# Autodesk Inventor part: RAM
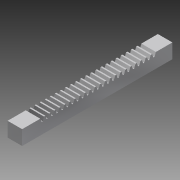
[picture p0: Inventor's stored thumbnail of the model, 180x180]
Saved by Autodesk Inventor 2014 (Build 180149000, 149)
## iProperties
Shininess: 64.0
Length Units: 11272
Angle Units: 11279
Time Units: 11290
Mass Units: 11286
Length Display Precision: 3
Angle Display Precision: 2
Compacted: True
Part Number: RAM
Document SubType Name: Modeling
Created: 2003-11
Designer: Autodesk, Inc.
Manufacturer: Standard
Standards Organization: Custom
Mass: 509.763 g
Surface Area: 178.528 cm^2
Volume: 65.0208 cm^3
Density: 7.84 g/cm^3
Material: Steel, High Strength Low Alloy
Appearance: Chrome
Density: 0.0
Volumn: 0.0
Area: 0.0
PropertySet Name: Model Information
Control State: 0
Master: False
Checked Out: False
Author: Autodesk, Inc.
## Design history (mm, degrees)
sketch "Sketch1"
  geometry: L1 (0, 0)-(19.05, 0); L2 (19.05, 0)-(19.05, 19.05); L3 (19.05, 19.05)-(0, 19.05); L4 (0, 19.05)-(0, 0)
  constraints: 8 end point, 2 parallel, 1 horizontal, 1 perpendicular
  dimensions: "d0" = 19.05 distance of L1.start L1.end; "d1" = 19.05 distance of L1.end L2.end
extrude "Extrusion1" new body sketch "Sketch1" distance "d2" = 196.85; taper "d3" = 0 deg
sketch "Sketch2"
  geometry: L1 (0, 0)-(0, 19.05) reference; L2 (0, 19.05)-(-196.85, 19.05) reference; L3 (-196.85, 19.05)-(-196.85, 0) reference; L4 (0, 0)-(-196.85, 0) reference; L5 (-168.185, 19.05)-(-166.4, 19.05); L6 (-166.4, 19.05)-(-164.739, 14.486); L7 (-168.185, 19.05)-(-169.846, 14.486); L8 (-167.293, 19.05)-(-167.293, 27.541); L9 (-130.145, 19.823)-(-130.145, 4.561); L10 (-173.431, 16.934)-(-94.815, 16.934); L11 (-163.197, 14.486)-(-161.535, 19.05); L12 (-161.535, 19.05)-(-159.751, 19.05); L13 (-159.751, 19.05)-(-158.089, 14.486); L14 (-164.739, 14.486)-(-163.197, 14.486); L15 (-158.089, 14.486)-(-24.993, 14.486); L16 (-160.643, 19.05)-(-160.643, 25.268); L17 (-169.846, 14.486)-(-171.389, 14.486); L18 (-171.389, 14.486)-(-173.05, 19.05); L19 (-156.542, 14.486)-(-154.881, 19.05); L20 (-154.881, 19.05)-(-153.096, 19.05); L21 (-153.096, 19.05)-(-151.435, 14.486); L22 (-149.887, 14.486)-(-148.226, 19.05); L23 (-148.226, 19.05)-(-146.441, 19.05); L24 (-146.441, 19.05)-(-144.78, 14.486); L25 (-143.232, 14.486)-(-141.571, 19.05); L26 (-141.571, 19.05)-(-139.786, 19.05); L27 (-139.786, 19.05)-(-138.125, 14.486); L28 (-136.578, 14.486)-(-134.916, 19.05); L29 (-134.916, 19.05)-(-133.132, 19.05); L30 (-133.132, 19.05)-(-131.47, 14.486); L31 (-129.923, 14.486)-(-128.261, 19.05); L32 (-128.261, 19.05)-(-126.477, 19.05); L33 (-126.477, 19.05)-(-124.815, 14.486); L34 (-123.268, 14.486)-(-121.607, 19.05); L35 (-121.607, 19.05)-(-119.822, 19.05); L36 (-119.822, 19.05)-(-118.161, 14.486); L37 (-116.613, 14.486)-(-114.952, 19.05); L38 (-114.952, 19.05)-(-113.167, 19.05); L39 (-113.167, 19.05)-(-111.506, 14.486); L40 (-109.958, 14.486)-(-108.297, 19.05); L41 (-108.297, 19.05)-(-106.512, 19.05); L42 (-106.512, 19.05)-(-104.851, 14.486); L43 (-103.304, 14.486)-(-101.642, 19.05); L44 (-101.642, 19.05)-(-99.858, 19.05); L45 (-99.858, 19.05)-(-98.196, 14.486); L46 (-96.649, 14.486)-(-94.987, 19.05); L47 (-94.987, 19.05)-(-93.203, 19.05); L48 (-93.203, 19.05)-(-91.541, 14.486); L49 (-89.994, 14.486)-(-88.333, 19.05); L50 (-88.333, 19.05)-(-86.548, 19.05); L51 (-86.548, 19.05)-(-84.887, 14.486); L52 (-83.339, 14.486)-(-81.678, 19.05); L53 (-81.678, 19.05)-(-79.893, 19.05); L54 (-79.893, 19.05)-(-78.232, 14.486); L55 (-76.684, 14.486)-(-75.023, 19.05); L56 (-75.023, 19.05)-(-73.238, 19.05); L57 (-73.238, 19.05)-(-71.577, 14.486); L58 (-70.03, 14.486)-(-68.368, 19.05); L59 (-68.368, 19.05)-(-66.584, 19.05); L60 (-66.584, 19.05)-(-64.922, 14.486); L61 (-63.375, 14.486)-(-61.713, 19.05); L62 (-61.713, 19.05)-(-59.929, 19.05); L63 (-59.929, 19.05)-(-58.267, 14.486); L64 (-56.72, 14.486)-(-55.059, 19.05)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; 65 further points
  constraints: 201 end point, 53 point on line, 27 collinear, 10 parallel, 3 perpendicular, 2 midpoint, 1 coincident, 1 horizontal, 200 other
  dimensions: "d5" = 2.11582 distance between parallel lines of L10 L5; "d6" = 20 deg angle of L8 L7; "d7" = 20 deg angle of L6 L8; "d11" = 6.64972 distance between parallel lines of L16 L8; "d12" = 3.32486 distance of point (-165.63, 16.934) point (-168.955, 16.934); "d13" = 3.32486 distance of point (-158.981, 16.934) point (-162.306, 16.934) (= d12); "d14" = 3.32486 distance of point (-168.955, 16.934) point (-172.28, 16.934) (= d12); "d15" = 23.7998 distance from line of L3 L18.end; "d16" = 2.44856 distance between parallel lines of L17 L10; "d19" = 6.6548 distance of L11.start L19.start
extrude "Extrusion2" sketch "Sketch2" stored distance "d24" = 25.4; taper "d25" = 0 deg
sketch "Sketch5"
  geometry: L1 (126.82, 14.486)-(128.482, 19.05) reference; L2 (125.273, 14.486)-(126.82, 14.486) reference; L3 (123.612, 19.05)-(125.273, 14.486) reference; L4 (123.612, 19.05)-(121.827, 19.05) reference; L5 (120.166, 14.486)-(121.827, 19.05) reference; L6 (118.618, 14.486)-(120.166, 14.486) reference; L7 (116.957, 19.05)-(118.618, 14.486) reference; L8 (116.957, 19.05)-(115.172, 19.05) reference; L9 (113.511, 14.486)-(115.172, 19.05) reference; L10 (111.963, 14.486)-(113.511, 14.486) reference; L11 (110.302, 19.05)-(111.963, 14.486) reference; L12 (110.302, 19.05)-(108.517, 19.05) reference; L13 (106.856, 14.486)-(108.517, 19.05) reference; L14 (105.309, 14.486)-(106.856, 14.486) reference; L15 (103.647, 19.05)-(105.309, 14.486) reference; L16 (103.647, 19.05)-(101.863, 19.05) reference; L17 (100.201, 14.486)-(101.863, 19.05) reference; L18 (98.654, 14.486)-(100.201, 14.486) reference; L19 (96.992, 19.05)-(98.654, 14.486) reference; L20 (96.992, 19.05)-(95.208, 19.05) reference; L21 (93.546, 14.486)-(95.208, 19.05) reference; L22 (91.999, 14.486)-(93.546, 14.486) reference; L23 (90.338, 19.05)-(91.999, 14.486) reference; L24 (90.338, 19.05)-(88.553, 19.05) reference; L25 (86.892, 14.486)-(88.553, 19.05) reference; L26 (85.344, 14.486)-(86.892, 14.486) reference; L27 (83.683, 19.05)-(85.344, 14.486) reference; L28 (83.683, 19.05)-(81.898, 19.05) reference; L29 (80.237, 14.486)-(81.898, 19.05) reference; L30 (78.689, 14.486)-(80.237, 14.486) reference; L31 (77.028, 19.05)-(78.689, 14.486) reference; L32 (77.028, 19.05)-(75.243, 19.05) reference; L33 (73.582, 14.486)-(75.243, 19.05) reference; L34 (72.035, 14.486)-(73.582, 14.486) reference; L35 (70.373, 19.05)-(72.035, 14.486) reference; L36 (70.373, 19.05)-(68.589, 19.05) reference; L37 (66.927, 14.486)-(68.589, 19.05) reference; L38 (65.38, 14.486)-(66.927, 14.486) reference; L39 (63.718, 19.05)-(65.38, 14.486) reference; L40 (63.718, 19.05)-(61.934, 19.05) reference; L41 (60.272, 14.486)-(61.934, 19.05) reference; L42 (58.725, 14.486)-(60.272, 14.486) reference; L43 (57.064, 19.05)-(58.725, 14.486) reference; L44 (57.064, 19.05)-(55.279, 19.05) reference; L45 (53.618, 14.486)-(55.279, 19.05) reference; L46 (52.07, 14.486)-(53.618, 14.486) reference; L47 (50.409, 19.05)-(52.07, 14.486) reference; L48 (50.409, 19.05)-(48.624, 19.05) reference; L49 (46.963, 14.486)-(48.624, 19.05) reference; L50 (45.415, 14.486)-(46.963, 14.486) reference; L51 (43.754, 19.05)-(45.415, 14.486) reference; L52 (43.754, 19.05)-(41.969, 19.05) reference; L53 (40.308, 14.486)-(41.969, 19.05) reference; L54 (38.761, 14.486)-(40.308, 14.486) reference; L55 (37.099, 19.05)-(38.761, 14.486) reference; L56 (37.099, 19.05)-(35.315, 19.05) reference; L57 (33.653, 14.486)-(35.315, 19.05) reference; L58 (32.111, 14.486)-(33.653, 14.486) reference; L59 (30.45, 19.05)-(32.111, 14.486) reference; L60 (30.45, 19.05)-(28.665, 19.05) reference; L61 (27.004, 14.486)-(28.665, 19.05) reference; L62 (25.461, 14.486)-(27.004, 14.486) reference; L63 (23.8, 19.05)-(25.461, 14.486) reference; L64 (23.8, 19.05)-(0, 19.05) reference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
  constraints: 10 end point, 3 parallel, 2 collinear, 2 point on line
  dimensions: "d26" = 1.5494 distance of L94.end L95.end; "d27" = 1.905 distance of L68.end L93.end
extrude "Extrusion3" cut sketch "Sketch5" distance "d28" = 25.4; taper "d29" = 0 deg
body "Solid1"
node "Projected Loop1"
node "Projected Loop4"
other parameters: "d22" = 25.4
